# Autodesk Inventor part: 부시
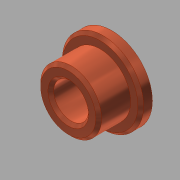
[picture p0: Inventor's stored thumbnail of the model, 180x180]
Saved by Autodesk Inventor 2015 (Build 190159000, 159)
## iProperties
Created: 2016-02
Part Number: 부시
Material: 강철, 연강
Document SubType Name: Modeling
Designer: test
Density: 1 g/cm^3
Appearance: 금속 1400F 열
Author: test
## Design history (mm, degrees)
sketch "스케치1"
  geometry: C1 r 14 at (0, 0); C2 r 10.5 at (0, 0); 1 further point
  constraints: 2 centre point, 2 coincident
  dimensions: "d0" = 28 diameter of C1; "d1" = 21 diameter of C2
extrude "돌출1" new body sketch "스케치1" distance "d2" = 4; taper "d3" = 0 deg
extrude "돌출2" join sketch "스케치1" distance "d4" = 11; taper "d5" = 0 deg
hole "구멍1" diameter "d8" = 12; stored, may be unused: countersink angle "d12" = 90 deg, drill point angle "d14" = 118 deg; dims "d6" = 10, "d7" = 10, "d9" = 6, "d10" = 4, "d11" = 2, "d13" = 8
chamfer "모따기1" distance "d15" = 1; stored, may be unused: second distance "d16" = 2, angle "d17" = 45 deg
chamfer "모따기2" distance "d18" = 1; stored, may be unused: second distance "d19" = 2, angle "d20" = 45 deg
node "솔리드1"
